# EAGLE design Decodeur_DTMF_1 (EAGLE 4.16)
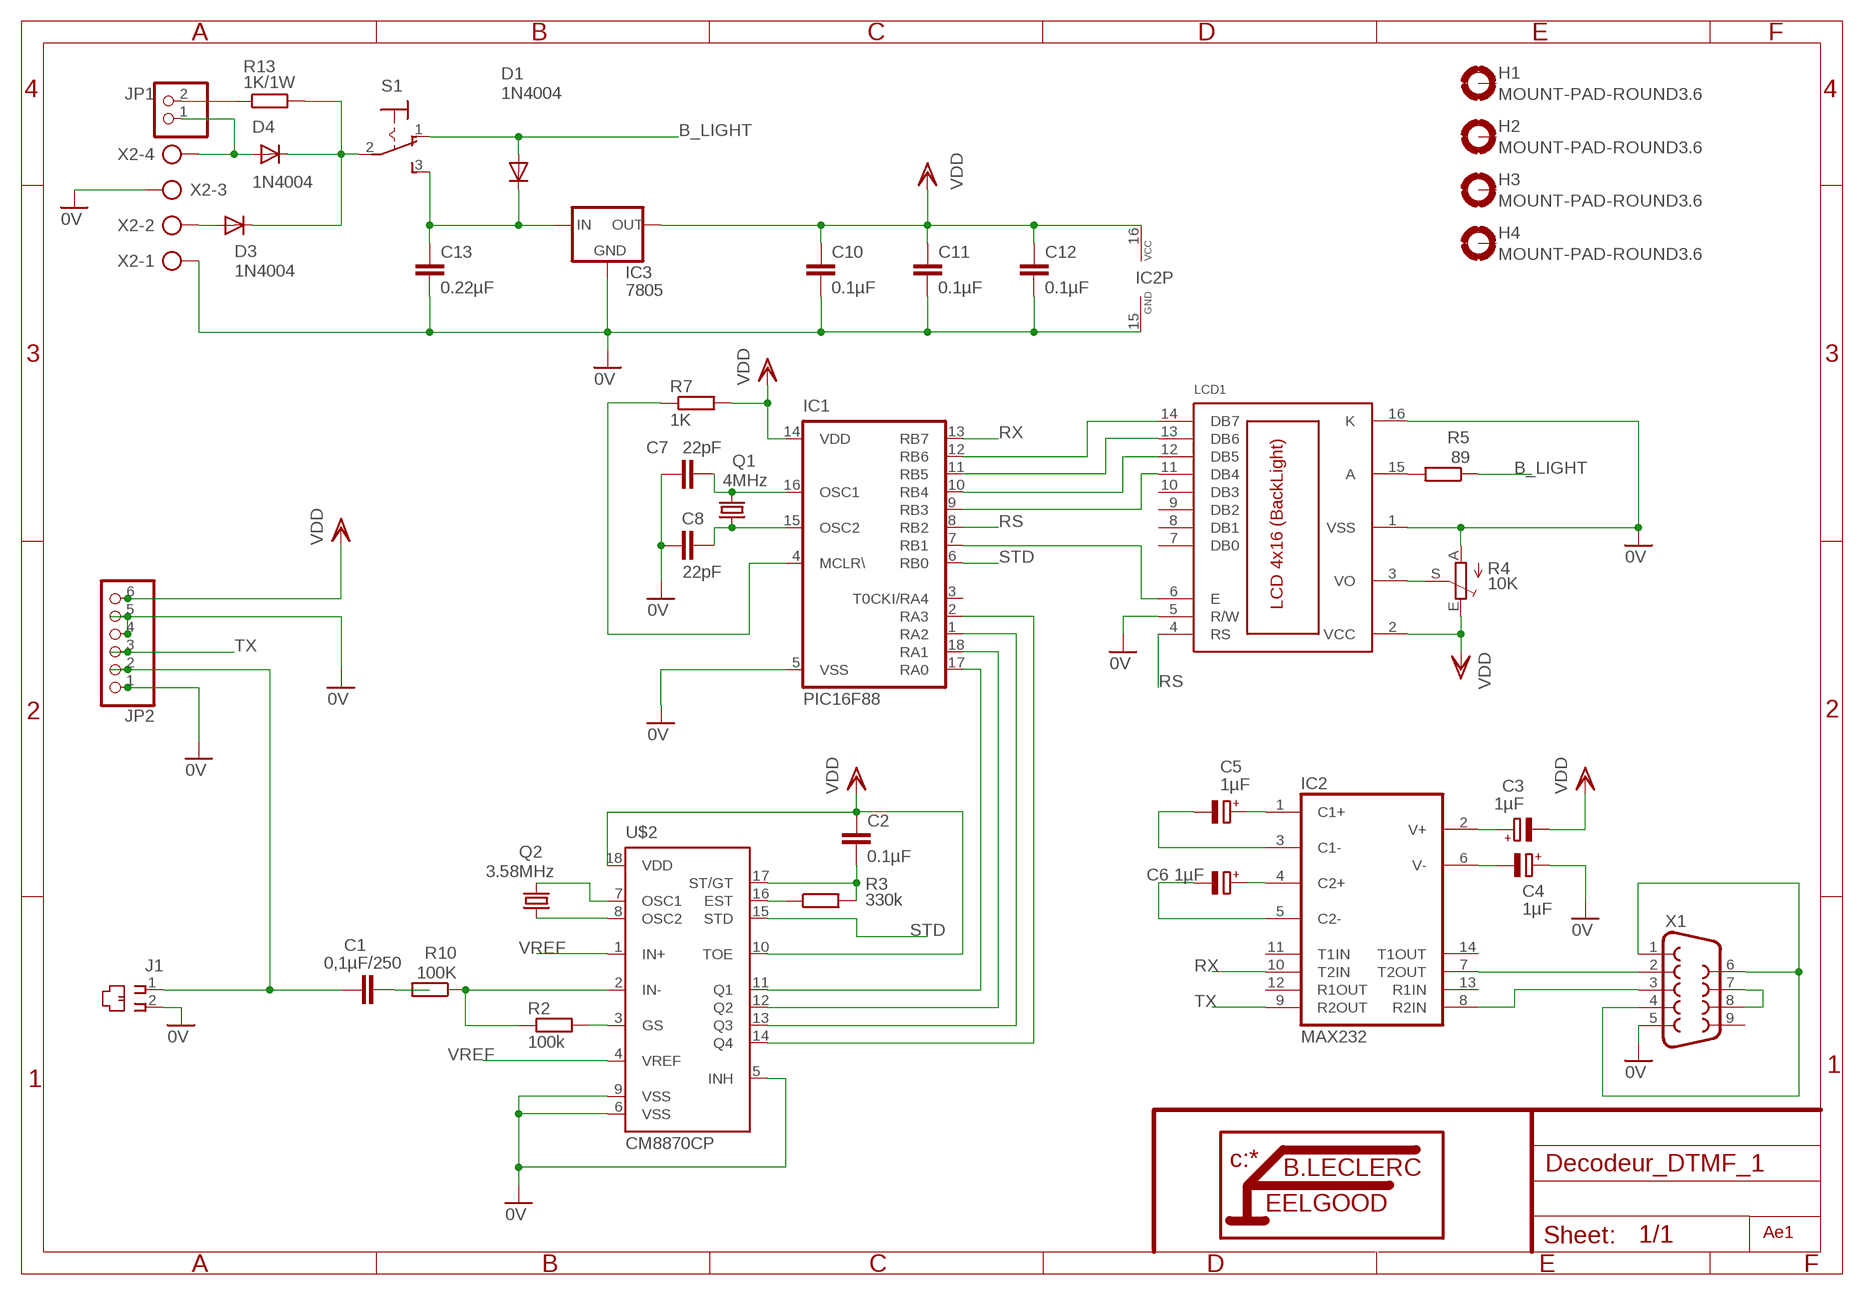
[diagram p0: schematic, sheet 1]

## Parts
C1  0,1µF/250  C-EU075-042X103  [C075-042X103]
C2  0.1µF  C-EU075-032X103  [C075-032X103]
C3  1µF  CPOL-EUE2.5-5  [E2,5-5]
C4  1µF  CPOL-EUE2.5-5  [E2,5-5]
C5  1µF  CPOL-EUE2.5-5  [E2,5-5]
C6  1µF  CPOL-EUE2.5-5  [E2,5-5]
C7  22pF  C-EU025-025X050  [C025-025X050]
C8  22pF  C-EU025-025X050  [C025-025X050]
C10  0.1µF  C-EU075-032X103  [C075-032X103]
C11  0.1µF  C-EU075-032X103  [C075-032X103]
C12  0.1µF  C-EU075-032X103  [C075-032X103]
C13  0.22µF  C-EU075-042X103  [C075-042X103]
D1  1N4004  [DO41-10]
D3  1N4004  [DO41-10]
D4  1N4004  [DO41-10]
H1  MOUNT-PAD-ROUND3.6  [3,6-PAD]
H2  MOUNT-PAD-ROUND3.6  [3,6-PAD]
H3  MOUNT-PAD-ROUND3.6  [3,6-PAD]
H4  MOUNT-PAD-ROUND3.6  [3,6-PAD]
IC1  PIC16F88  PIC16F84AP  [DIL18]
IC2  MAX232  [DIL16]
IC3  7805  78XXL  [78XXL]
J1  215876-7  [215876-7]
JP1  PINHD-1X2  [1X02]
JP2  PINHD-1X6  [1X06]
LCD1  LCD_4X16  [MC1604BW_SYL]
Q1  4MHz  CRYTALHC49S  [HC49/S]
Q2  3.58MHz  CRYTALHC49S  [HC49/S]
R2  100k  R-EU_0207/10  [0207/10]
R3  330k  R-EU_0207/10  [0207/10]
R4  10K  TRIM_EU-LI10  [LI10]
R5  89  R-EU_0207/10  [0207/10]
R7  1K  R-EU_0207/10  [0207/10]
R10  100K  R-EU_0207/10  [0207/10]
R13  1K/1W  R-EU_0309/12  [0309/12]
S1  320-916  [320-916]
U$2  CM8870CP  [DIL18]
X1  F09H  [F09H]
X2  AK300/4  [AK300/4]

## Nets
0V: C4.+ C7.1 C8.1 C10.2 C11.2 C12.2 C13.2 IC1.5(VSS) IC2.15(GND) IC3.GND J1.2 JP2.1 JP2.4 JP2.5 LCD1.1(VSS) LCD1.5(R/W) LCD1.16(K) R4.A U$2.5(INH) U$2.6(VSS) U$2.9(VSS) X1.5 X2.1 X2.3
B_LIGHT: D1.A R5.1 S1.1(O)
N$1: Q2.1 U$2.8(OSC2)
N$2: Q2.2 U$2.7(OSC1)
N$3: R2.2 U$2.3(GS)
N$4: R2.1 R10.1 U$2.2(IN-)
N$6: IC2.7(T2OUT) X1.2
N$8: R3.1 U$2.16(EST)
N$9: C2.2 R3.2 U$2.17(ST/GT)
N$10: C13.1 D1.C IC3.IN S1.3(S)
N$12: C4.- IC2.6(V-)
N$13: LCD1.15(A) R5.2
N$14: C3.+ IC2.2(V+)
N$15: IC1.7(RB1) LCD1.6(E)
N$16: C5.+ IC2.1(C1+)
N$17: C5.- IC2.3(C1-)
N$18: C6.+ IC2.4(C2+)
N$19: C6.- IC2.5(C2-)
N$20: LCD1.3(VO) R4.S
N$21: IC1.9(RB3) LCD1.11(DB4)
N$22: IC1.10(RB4) LCD1.12(DB5)
N$23: C8.2 IC1.15(OSC2) Q1.1
N$26: IC1.4(MCLR\) R7.1
N$27: C1.2 R10.2
N$31: C1.1 J1.1 JP2.2
N$33: D3.A X2.2
N$34: D3.C D4.C R13.2 S1.2(P)
N$35: D4.A JP1.1 X2.4
N$36: IC1.11(RB5) LCD1.13(DB6)
N$37: IC1.12(RB6) LCD1.14(DB7)
N$38: IC1.17(RA0) U$2.11(Q1)
N$39: IC1.18(RA1) U$2.12(Q2)
N$40: IC1.1(RA2) U$2.13(Q3)
N$41: IC1.2(RA3) U$2.14(Q4)
N$43: JP1.2 R13.1
N$45: X1.1 X1.4 X1.6
N$46: X1.7 X1.8
N$47: IC2.8(R2IN) X1.3
N$83: C7.2 IC1.16(OSC1) Q1.2
RS: IC1.8(RB2) LCD1.4(RS)
RX: IC1.13(RB7) IC2.10(T2IN)
STD: IC1.6(RB0) U$2.15(STD)
TX: IC2.9(R2OUT) JP2.3
VDD: C2.1 C3.- C10.1 C11.1 C12.1 IC1.14(VDD) IC2.16(VCC) IC3.OUT JP2.6 LCD1.2(VCC) R4.E R7.2 U$2.10(TOE) U$2.18(VDD)
VREF: U$2.1(IN+) U$2.4(VREF)
Unconnected: H1.B3,6(MOUNT) H2.B3,6(MOUNT) H3.B3,6(MOUNT) H4.B3,6(MOUNT) IC1.3(T0CKI/RA4) IC2.11(T1IN) IC2.12(R1OUT) IC2.13(R1IN) IC2.14(T1OUT) LCD1.7(DB0) LCD1.8(DB1) LCD1.9(DB2) LCD1.10(DB3) X1.9

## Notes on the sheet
- Ae1

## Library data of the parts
C1 C2 C7 C8 C10-C13 = rcl:C-EU: CAPACITOR, European symbol
C3-C6 = rcl:CPOL-EU: POLARIZED CAPACITOR, European symbol
D1 D3 D4 = diode:1N4004: DIODE
H1-H4 = holes:MOUNT-PAD-ROUND: MOUNTING PAD, round
IC1 = microchip:PIC16F8*: MICROCONTROLLER 8-Bit PIC16F8X Family - CMOS Flash/EEPROM Pin Compatible : PIC16F83, PIC16CR83, PIC16F84A, PIC16CR84 see also PIC16C*
IC2 = maxim:MAX232: RS232 TRANSEIVER
IC3 = v-reg:78XXL: VOLTAGE REGULATOR
J1 = con-amp:215876-7: AMP connector
JP1 = pinhead:PINHD-1X2: PIN HEADER
JP2 = pinhead:PINHD-1X6: PIN HEADER
LCD1 = lcd_4x16_backlight:LCD_4X16
Q1 Q2 = crystal:CRYTAL: CRYSTAL
R2 R3 R5 R7 R10 R13 = rcl:R-EU_: RESISTOR, European symbol
R4 = pot:TRIM_EU-: POTENTIOMETER
S1 = switch:320-916: TOGGLE SWITCH distributor RS Components
U$2 = california-micro-devices:CM8870C: CMOS Integrated DTMF Receiver cm8870.pdf
X1 = con-subd:F09: SUB-D
X2 = con-ptr500:AK300/4: CONNECTOR

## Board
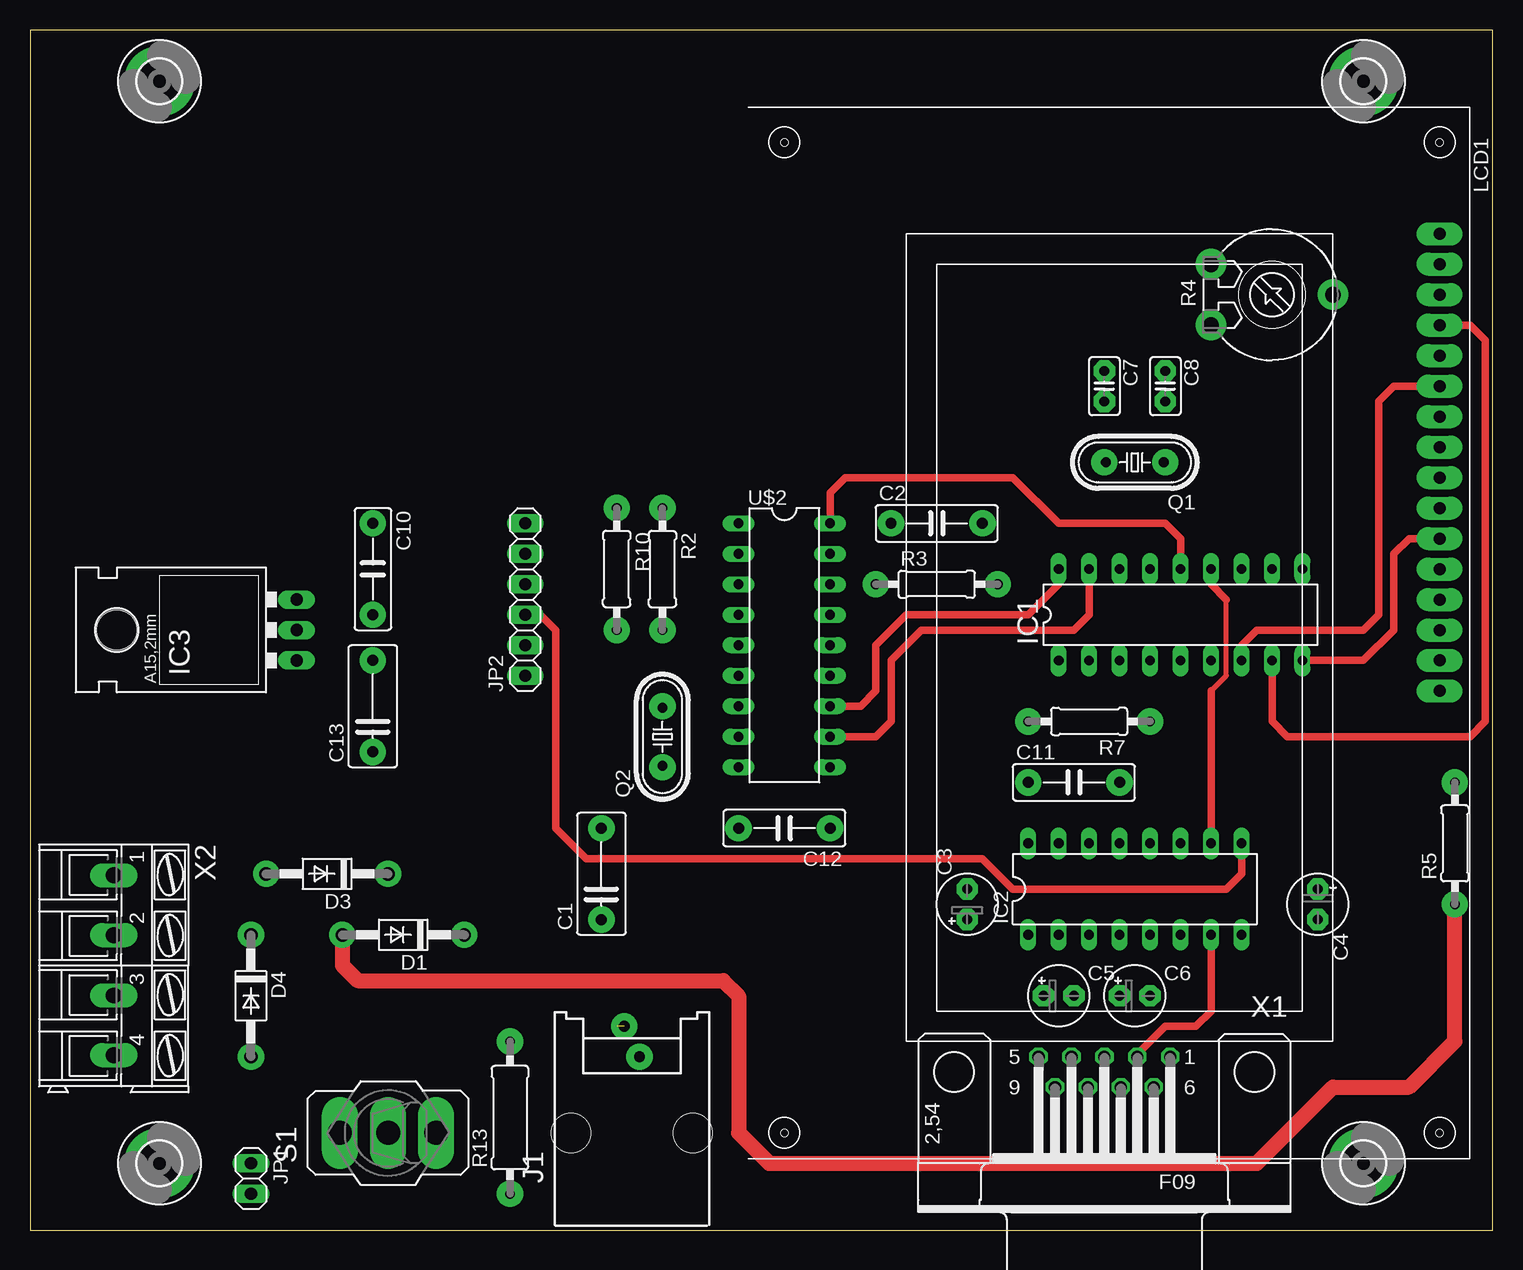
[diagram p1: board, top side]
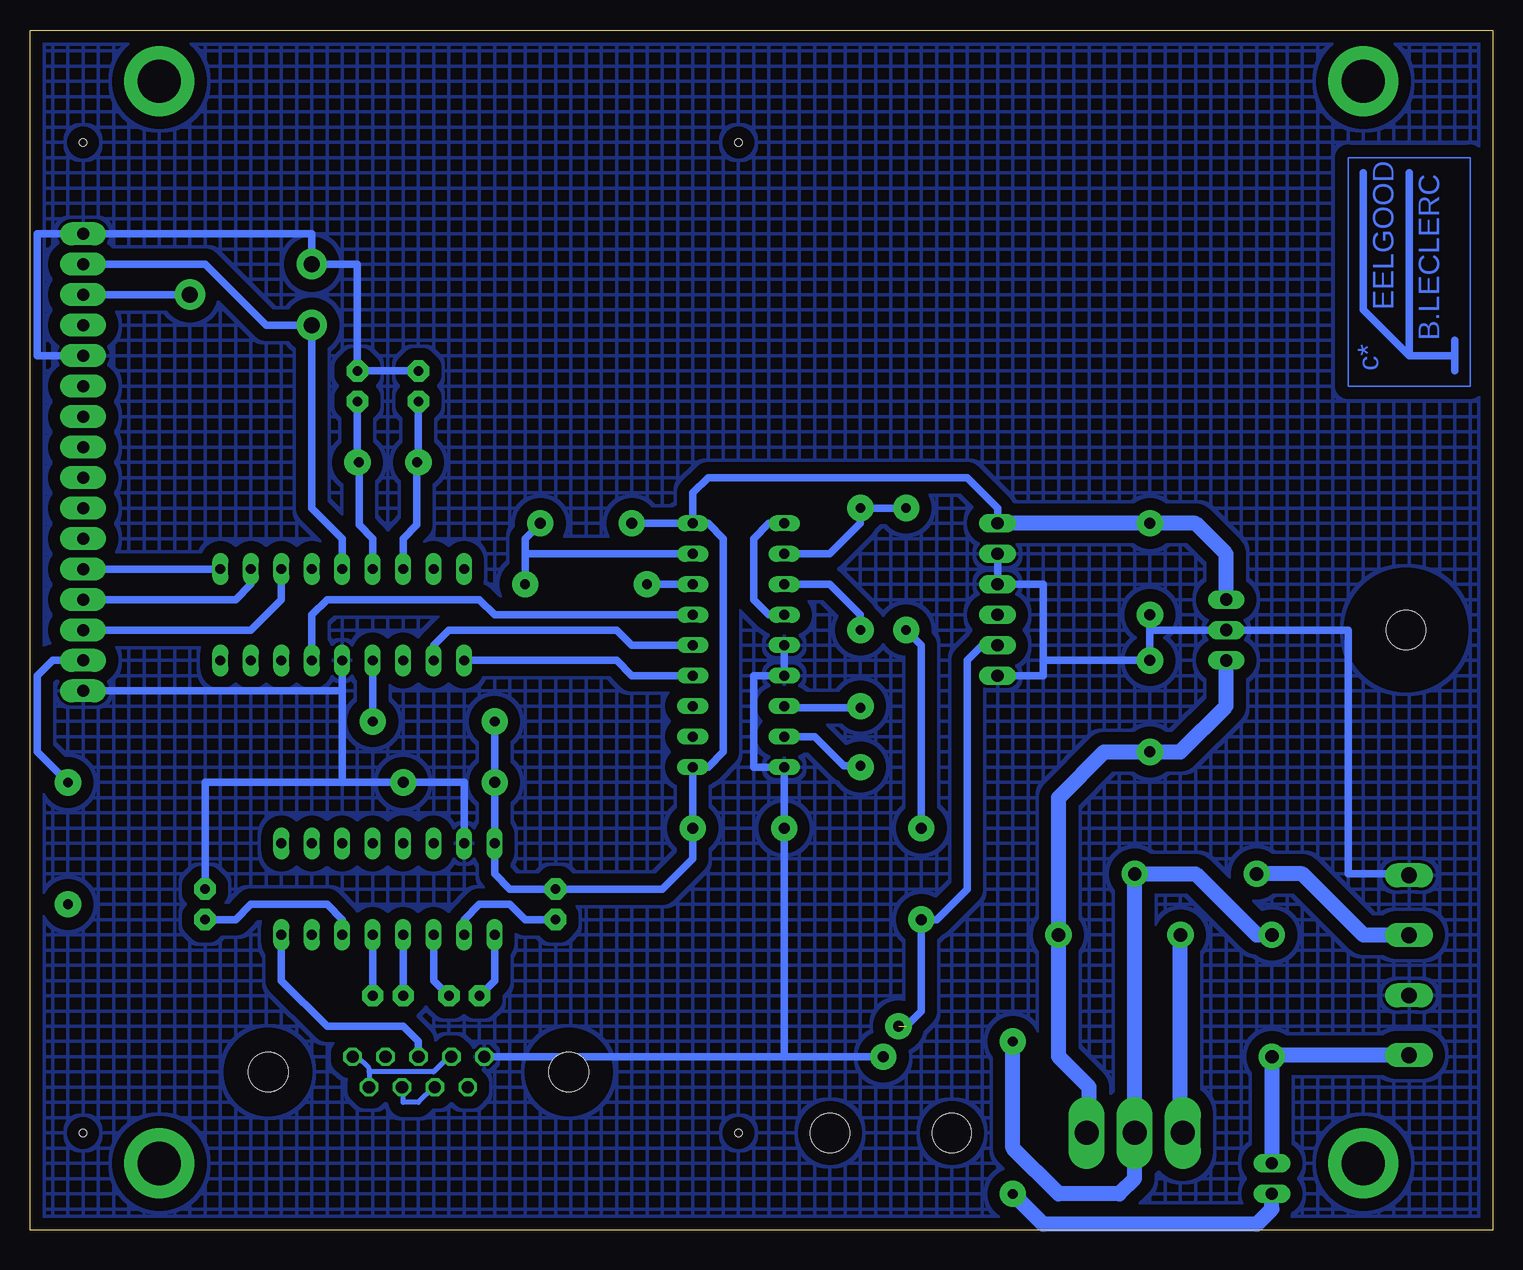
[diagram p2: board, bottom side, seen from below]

Size 121.9 x 100 mm. Coordinates in mm from the lower left corner, seen from the top.
Outline: 0,0 121.9,0 121.9,100 0,100 0,0
Copper layers (1*16): Top 0.035mm / dielectric 1.5mm / Bottom 0.035mm
Design rules "default": minimum track width 10mil, minimum drill 24mil, track to track 8mil, track to pad 8mil, pad to pad 8mil, via to via 8mil, smd to smd 8mil, copper to edge 40mil, drill to drill 8mil, minimum pad ring 10mil, minimum via ring 8mil, stop-mask expansion 4mil, vias tented up to drill 0mil, thermal gap 10mil

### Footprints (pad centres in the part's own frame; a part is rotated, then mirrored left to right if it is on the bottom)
C075-042X103 = drill 0.914 octagon: 1 -3.81,0; 2 3.81,0
C075-032X103 = drill 0.914 octagon: 1 -3.81,0; 2 3.81,0
E2,5-5 = drill 0.813 pad 1.6 round: + -1.27,0 | drill 0.813 pad 1.6 octagon: - 1.27,0
C025-025X050 = drill 0.813 octagon: 1 -1.27,0; 2 1.27,0
DO41-10 = drill 1.118 round: A 5.08,0; C -5.08,0
3,6-PAD = drill 3.6 pad 5.842 round: B3,6 0,0
DIL18 = drill 0.813 long: 1 -10.16,-3.81; 2 -7.62,-3.81; 3 -5.08,-3.81; 4 -2.54,-3.81; 5 0,-3.81; 6 2.54,-3.81; 7 5.08,-3.81; 8 7.62,-3.81; 9 10.16,-3.81; 10 10.16,3.81; 11 7.62,3.81; 12 5.08,3.81; 13 2.54,3.81; 14 0,3.81; 15 -2.54,3.81; 16 -5.08,3.81; 17 -7.62,3.81; 18 -10.16,3.81
DIL16 = drill 0.813 long: 1 -8.89,-3.81; 2 -6.35,-3.81; 3 -3.81,-3.81; 4 -1.27,-3.81; 5 1.27,-3.81; 6 3.81,-3.81; 7 6.35,-3.81; 8 8.89,-3.81; 9 8.89,3.81; 10 6.35,3.81; 11 3.81,3.81; 12 1.27,3.81; 13 -1.27,3.81; 14 -3.81,3.81; 15 -6.35,3.81; 16 -8.89,3.81
78XXL = drill 1.016 long: GND 0,-3.81; IN -2.54,-3.81; OUT 2.54,-3.81 | hole 3.302: 0,11.176
215876-7 = drill 0.889 round: 1 -0.635,8.89; 2 0.635,6.35 | hole 3.251: -5.08,0; 5.08,0
1X02 = drill 1.016 long: 1 -1.27,0; 2 1.27,0
1X06 = drill 1.016 long: 1 -6.35,0; 2 -3.81,0; 3 -1.27,0; 4 1.27,0; 5 3.81,0; 6 6.35,0
MC1604BW_SYL = drill 1 pad 1.93 long: 1 2.54,0; 2 5.08,0; 3 7.62,0; 4 10.16,0; 5 12.7,0; 6 15.24,0; 7 17.78,0; 8 20.32,0; 9 22.86,0; 10 25.4,0; 11 27.94,0; 12 30.48,0; 13 33.02,0; 14 35.56,0; 15 38.1,0; 16 40.64,0 | hole 0.6: -5.08,0; 77.47,0; -5.08,-54.61; 77.47,-54.61
HC49/S = drill 0.813 round: 1 -2.413,0; 2 2.413,0
0207/10 = drill 0.813 octagon: 1 -5.08,0; 2 5.08,0
LI10 = drill 1.321 octagon: A -2.54,-5.08; E 2.54,-5.08; S 0,5.08
0309/12 = drill 0.813 octagon: 1 -6.35,0; 2 6.35,0
320-916 = drill 2.007 long: 1 0,4.013; 2 0,0; 3 0,-4.013
F09H = drill 1.016 octagon: 1 -5.486,-1.27; 2 -2.743,-1.27; 3 0,-1.27; 4 2.743,-1.27; 5 5.486,-1.27; 6 -4.115,1.27; 7 -1.372,1.27; 8 1.372,1.27; 9 4.115,1.27 | hole 3.302: -12.522,0; 12.522,0
AK300/4 = drill 1.321 long: 1 -7.493,0; 2 -2.515,0; 3 2.515,0; 4 7.493,0

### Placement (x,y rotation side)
C1  47.62,29.68 90 top
C2  75.56,58.89 0 top
C3  78.1,27.14 90 top
C4  107.31,27.14 270 top
C5  85.72,19.52 0 top
C6  92.07,19.52 0 top
C7  89.53,70.32 270 top
C8  94.61,70.32 270 top
C10  28.57,55.08 270 top
C11  86.99,37.3 0 top
C12  62.86,33.49 180 top
C13  28.57,43.65 90 top
D1  31.11,24.6 180 top
D3  24.76,29.68 180 top
D4  18.41,19.52 270 top
H1  10.79,5.55 0 top
H2  10.79,95.72 0 top
H3  111.12,5.55 0 top
H4  111.12,95.72 0 top
IC1  95.88,51.27 0 top
IC2  92.07,28.41 0 top
IC3  18.41,50 90 top
J1  50.16,8.09 0 top
JP1  18.41,4.28 270 top
JP2  41.27,52.54 90 top
LCD1  117.47,85.56 270 top
Q1  92.07,63.97 180 top
Q2  52.7,41.11 90 top
R2  52.7,55.08 270 top
R3  75.56,53.81 0 top
R4  103.5,77.94 270 top
R5  118.74,32.22 90 top
R7  88.26,42.38 180 top
R10  48.89,55.08 270 top
R13  40,9.36 90 top
S1  29.84,8.09 90 top
U$2  62.86,48.73 270 top
U$3  [LITTFEEL]  -0.64,72.86 90 bottom
X1  89.53,13.17 180 top
X2  6.98,22.06 270 top

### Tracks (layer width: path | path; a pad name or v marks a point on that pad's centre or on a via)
0V
  Bottom 0.61: 84.45,14.44 X1.5 59.05,14.44 | LCD1.5 121.28,72.86 121.28,83.02 LCD1.1 98.42,83.02 R4.A 94.61,80.48 C8.1 C7.1 | 95.88,44.92 LCD1.16 | 95.88,37.3 95.88,44.92 | 95.88,37.3 C11.2 85.72,37.3 IC2.15 | 95.88,44.92 IC1.5 | 95.88,37.3 107.31,37.3 C4.+ | J1.2 59.05,14.44 | 59.05,14.44 C12.2 U$2.9 61.59,38.57 61.59,46.19 U$2.6 U$2.5 | 37.46,47.46 C13.2 28.57,50 | 37.46,47.46 37.46,46.19 JP2.1 | 28.57,50 C10.2 | 28.57,50 IC3.GND 12.06,50 12.06,29.68 6.98,29.68 X2.1 | 37.46,47.46 37.46,53.81 JP2.4 JP2.5
  pour Bottom (isolate 1.016, hatched): 0.63,0.47 0.63,99.53 121.28,99.53 121.28,0.47
B_LIGHT
  Top 1.27: R5.1 118.74,15.71 114.93,11.9 108.58,11.9 102.23,5.55 61.59,5.55 59.05,8.09 59.05,19.52 57.78,20.79 27.3,20.79 26.03,22.06 D1.A
  Bottom 1.27: S1.1 26.03,8.09 D1.A
N$1
  Bottom 0.61: Q2.1 54.1,38.7 56.51,41.11 U$2.8
N$2
  Bottom 0.61: Q2.2 58.92,43.52 U$2.7
N$3
  Bottom 0.61: R2.2 52.7,51.27 55.24,53.81 U$2.3
N$4
  Bottom 0.61: R10.1 R2.1 52.7,58.89 55.24,56.35 U$2.2
N$5  (via drill 0.6 pad 2.18)
  other vias: 28.57,58.89
N$6
  Top 0.61: X1.2 92.27,14.64 94.61,16.98 97.15,16.98 98.42,18.25 IC2.7
N$7  (via drill 0.6 pad 2.18)
  other vias: 28.57,39.84
N$8
  Bottom 0.61: U$2.16 R3.1
N$9
  Bottom 0.61: 80.64,56.35 R3.2 | 80.64,56.35 80.64,57.62 C2.2 | U$2.17 80.64,56.35
N$10
  Bottom 1.27: IC3.IN 22.22,43.65 26.03,39.84 C13.1 32.38,39.84 36.19,36.03 D1.C 36.19,14.44 33.65,11.9 33.65,8.09 S1.3
N$11  (via drill 0.6 pad 2.18)
  other vias: 48.89,60.16
N$12
  Bottom 0.61: IC2.6 95.88,25.87 97.15,27.14 103.5,27.14 104.77,25.87 C4.-
N$13
  Bottom 0.61: R5.2 121.28,39.84 121.28,46.19 120.01,47.46 LCD1.15
N$14
  Bottom 0.61: C3.+ 80.64,25.87 81.91,27.14 84.45,27.14 85.72,25.87 IC2.2
N$15
  Top 0.61: IC1.7 100.96,48.73 102.23,50 111.12,50 112.39,51.27 112.39,69.05 113.66,70.32 LCD1.6
N$16
  Bottom 0.61: IC2.1 83.18,20.79 C5.+
N$17
  Bottom 0.61: IC2.3 88.26,20.79 C5.-
N$18
  Bottom 0.61: C6.+ IC2.4
N$19
  Bottom 0.61: C6.- IC2.5
N$20
  Bottom 0.61: R4.S LCD1.3
N$21
  Top 0.61: IC1.9 111.12,47.46 113.66,50 113.66,56.35 114.93,57.62 LCD1.11
N$22
  Bottom 0.61: IC1.10 LCD1.12
N$23
  Bottom 0.61: C8.2 94.61,63.97 Q1.1 94.48,58.76 93.34,57.62 IC1.15
N$24  (via drill 0.6 pad 2.18)
  other vias: 48.89,50
N$25  (via drill 0.6 pad 2.18)
  other vias: 52.7,43.65
N$26
  Bottom 0.61: R7.1 IC1.4
N$27
  Bottom 0.61: R10.2 47.62,48.73 C1.2
N$28  (via drill 0.6 pad 2.18)
  other vias: 66.67,33.49
N$29  (via drill 0.6 pad 2.18)
  other vias: 79.37,58.89
N$30  (via drill 0.6 pad 2.18)
  other vias: 80.64,53.81
N$31  (1 unrouted)
  Bottom 0.61: 50.16,16.98 48.89,16.98 47.62,18.25 C1.1 46.35,25.87 43.81,28.41 43.81,47.46 42.54,48.73 JP2.2
N$32  (via drill 0.6 pad 2.18)
  other vias: 89.53,63.97
N$33
  Bottom 1.27: X2.2 10.77,24.57 15.87,29.68 D3.A
N$34
  Bottom 1.27: D4.C 19.68,24.6 24.76,29.68 D3.C S1.2 29.84,4.28 31.11,3.01 36.19,3.01 40,6.82 R13.2
N$35
  Bottom 1.27: X2.4 18.28,14.57 D4.A JP1.1
N$36
  Bottom 0.61: LCD1.13 104.77,52.54 103.5,53.81 IC1.11
N$37
  Bottom 0.61: LCD1.14 103.5,50 100.96,52.54 IC1.12
N$38
  Top 0.61: IC1.17 88.26,51.27 86.99,50 74.29,50 71.75,47.46 71.75,42.38 70.48,41.11 U$2.11
N$39
  Top 0.61: IC1.18 85.72,53.81 83.18,51.27 73.02,51.27 70.48,48.73 70.48,44.92 69.21,43.65 U$2.12
N$40
  Bottom 0.61: IC1.1 73.02,47.46 71.75,46.19 U$2.13
N$41
  Bottom 0.61: IC1.2 88.26,48.73 86.99,50 73.02,50 71.75,48.73 U$2.14
N$42  (via drill 0.6 pad 2.18)
  other vias: 93.34,42.38
N$43
  Bottom 1.27: JP1.2 18.41,1.74 19.68,0.47 37.46,0.47 R13.1
N$44  (via drill 0.6 pad 2.18)
  other vias: 90.8,37.3
N$45
  Bottom 0.406: 93.64,13.17 X1.6 | 93.64,13.17 93.64,13.48 94.61,14.44 | 86.99,14.44 88.26,13.17 93.64,13.17
  Bottom 0.61: 94.61,14.44 X1.1 | X1.4 86.99,14.44
N$46
  Bottom 0.406: 88.26,11.9 89.53,10.63 90.8,10.63 90.8,11.9
  Bottom 0.61: X1.8 88.26,11.9 | 90.8,11.9 X1.7
N$47
  Bottom 0.61: X1.3 89.53,15.71 90.8,16.98 97.15,16.98 100.96,20.79 IC2.8
N$48  (via drill 0.6 pad 2.18)
  other vias: 47.62,33.49
N$49  (via drill 0.6 pad 2.18)
  other vias: 36.19,24.6
N$50  (via drill 0.6 pad 2.18)
  other vias: 26.03,24.6
N$51  (via drill 0.6 pad 2.18)
  other vias: 18.41,24.6
N$52  (via drill 0.6 pad 2.18)
  other vias: 18.41,14.44
N$53  (via drill 0.6 pad 2.18)
  other vias: 29.84,29.68
N$54  (via drill 0.6 pad 2.18)
  other vias: 19.68,29.68
N$55  (via drill 0.6 pad 2.18)
  other vias: 47.62,25.87
N$56  (via drill 0.6 pad 2.18)
  other vias: 83.18,37.3
N$57  (via drill 0.6 pad 2.18)
  other vias: 83.18,42.38
N$58  (via drill 0.6 pad 2.18)
  other vias: 94.61,63.97
N$59  (via drill 0.6 pad 2.18)
  other vias: 70.48,53.81
N$60  (via drill 0.6 pad 2.18)
  other vias: 71.75,58.89
N$61  (via drill 0.6 pad 2.18)
  other vias: 59.05,33.49
N$62  (via drill 0.6 pad 2.18)
  other vias: 52.7,38.57
N$63  (via drill 0.6 pad 2.18)
  other vias: 52.7,50
N$64  (via drill 0.6 pad 2.18)
  other vias: 52.7,60.16
N$65  (via drill 0.6 pad 2.18)
  other vias: 28.57,47.46
N$66  (via drill 0.6 pad 2.18)
  other vias: 28.57,51.27
N$67  (via drill 0.6 pad 2.18)
  other vias: 40,15.71
N$68  (via drill 0.6 pad 2.18)
  other vias: 40,3.01
N$69  (via drill 0.6 pad 2.18)
  other vias: 118.74,27.14
N$70  (via drill 0.6 pad 2.18)
  other vias: 118.74,37.3
N$71  (via drill 0.6 pad 2.18)
  other vias: 49.53,16.98
N$72  (via drill 0.6 pad 2.54)
  other vias: 98.42,80.48
N$73  (via drill 0.6 pad 2.18)
  other vias: 50.8,14.44
N$74  (via drill 0.6 pad 2.54)
  other vias: 108.58,77.94
N$75  (via drill 0.6 pad 2.54)
  other vias: 98.42,75.4
N$76  (via drill 0.6 pad 1.78)
  other vias: 78.1,28.41
N$77  (via drill 0.6 pad 1.78)
  other vias: 78.1,25.87
N$78  (via drill 0.6 pad 1.78)
  other vias: 84.45,19.52
N$79  (via drill 0.6 pad 1.78)
  other vias: 86.99,19.52
N$80  (via drill 0.6 pad 1.78)
  other vias: 93.34,19.52
N$81  (via drill 0.6 pad 1.78)
  other vias: 90.8,19.52
N$82  (via drill 0.6 pad 1.78)
  other vias: 107.31,28.41
N$83
  Bottom 0.61: C7.2 89.53,63.97 Q1.2 89.66,58.76 90.8,57.62 IC1.16
N$84  (via drill 0.6 pad 1.78)
  other vias: 107.31,25.87
N$85  (via drill 0.6 pad 1.78)
  other vias: 94.61,69.05
N$86  (via drill 0.6 pad 1.78)
  other vias: 94.61,71.59
N$87  (via drill 0.6 pad 1.78)
  other vias: 89.53,71.59
N$88  (via drill 0.6 pad 1.78)
  other vias: 89.53,69.05
RS
  Top 0.61: IC1.8 103.5,42.38 104.77,41.11 120.01,41.11 121.28,42.38 121.28,74.13 120.01,75.4 LCD1.4
RX
  Top 0.406: 98.42,44.92 99.69,46.19 99.69,52.54
  Top 0.61: IC2.10 98.42,44.92 | 99.69,52.54 98.42,53.81 IC1.13
STD
  Bottom 0.61: IC1.6 98.42,51.27 97.15,52.54 84.45,52.54 83.18,51.27 U$2.15
TX
  Top 0.61: IC2.9 100.96,29.68 99.69,28.41 81.91,28.41 79.37,30.95 46.35,30.95 43.81,33.49 43.81,50 42.54,51.27 JP2.3
VDD
  Top 0.61: IC1.14 95.88,57.62 94.61,58.89 85.72,58.89 81.91,62.7 67.94,62.7 66.67,61.43 U$2.18
  Bottom 0.61: LCD1.2 107.31,80.48 102.23,75.4 R4.E 98.42,60.16 95.88,57.62 IC1.14 | R7.2 C11.1 IC2.16 83.18,29.68 81.91,28.41 C3.- 69.21,28.41 66.67,30.95 C12.1 U$2.10 65.4,38.57 64.13,39.84 64.13,57.62 65.4,58.89 C2.1 U$2.18 66.67,61.43 65.4,62.7 43.81,62.7 41.27,60.16 JP2.6
  Bottom 1.27: IC3.OUT 22.22,56.35 24.76,58.89 C10.1 JP2.6
VREF
  Bottom 0.61: U$2.4 60.32,51.27 61.59,52.54 61.59,57.62 60.32,58.89 U$2.1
